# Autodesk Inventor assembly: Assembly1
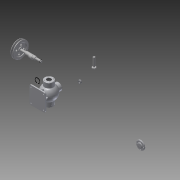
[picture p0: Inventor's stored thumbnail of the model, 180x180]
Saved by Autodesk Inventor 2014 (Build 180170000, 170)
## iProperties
Created: 2017-01
Part Number: Assembly1
Document SubType Name: Assembly
Designer: ksu
Author: ksu
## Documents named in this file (19)
- C:\Users\ksu\Desktop\470118V1012\Assembly1.iam
- C:\Users\ksu\Desktop\470118V1012\멈춤링- 15 x 1.ipt
- C:\Users\ksu\Desktop\470118V1012\멈춤링- 35x1.6.ipt
- KS B 1336 - 35x1.6.ipt
- C:\Users\ksu\Desktop\470118V1012\베어링- 6202.ipt
- KS B 2023 - 6202 - 15 x 35 x 11 - 7.8.ipt
- C:\Users\ksu\Desktop\470118V1012\본체.ipt
- C:\Users\ksu\Desktop\470118V1012\볼트 M4 x 12.ipt
- C:\Users\ksu\Desktop\470118V1012\볼트 M4 x 16.ipt
- C:\Users\ksu\Desktop\470118V1012\부시.ipt
- C:\Users\ksu\Desktop\470118V1012\상부커버.ipt
- C:\Users\ksu\Desktop\470118V1012\슬라이드.ipt
- C:\Users\ksu\Desktop\470118V1012\앞커버.ipt
- C:\Users\ksu\Desktop\470118V1012\오일실 15 30 7.ipt
- C:\Users\ksu\Desktop\470118V1012\키 4 x 4 x 12.ipt
- C:\Users\ksu\Desktop\470118V1012\편심축.ipt
- C:\Users\ksu\Desktop\470118V1012\V-벨트풀리.ipt
- C:\Users\ksu\Desktop\470118V1012\너트 M8.ipt
- C:\Users\ksu\Desktop\470118V1012\뒤커버.ipt
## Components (16 placed, 5 different names)
1. KS B 1336 - 35x1.6:1
2. KS B 2023 - 6202 - 15 x 35 x 11 - 7.8:1 — Mate:47, Mate:48
3. KS B 1021 - 에 따름 ISO 1207 - 미터 A  M 4 x 12:1 — Mate:25, Mate:44
4. ISO 4762 M4 x 16:1 — Mate:4, Mate:8
5. V-벨트풀리:1 — Mate:35, Mate:36
6. ISO 4762 M4 x 16:2 — Mate:11, Mate:12
7. ISO 4762 M4 x 16:3 — Mate:7, Mate:10
8. ISO 4762 M4 x 16:4 — Mate:6, Mate:9
9. ISO 4762 M4 x 16:5
10. ISO 4762 M4 x 16:6
11. ISO 4762 M4 x 16:7
12. ISO 4762 M4 x 16:8
13. KS B 1021 - 에 따름 ISO 1207 - 미터 A  M 4 x 12:2 — Mate:27, Mate:43
14. KS B 1021 - 에 따름 ISO 1207 - 미터 A  M 4 x 12:3 — Mate:26, Mate:45
15. KS B 1021 - 에 따름 ISO 1207 - 미터 A  M 4 x 12:4 — Mate:28, Mate:46
16. KS B 2023 - 6202 - 15 x 35 x 11 - 7.8:2 — Mate:49, Mate:50
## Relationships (22: Mate 22)
- Mate:4: ISO 4762 M4 x 16:1
- Mate:6: ISO 4762 M4 x 16:4
- Mate:7: ISO 4762 M4 x 16:3
- Mate:8: ISO 4762 M4 x 16:1
- Mate:9: ISO 4762 M4 x 16:4
- Mate:10: ISO 4762 M4 x 16:3
- Mate:11: ISO 4762 M4 x 16:2
- Mate:12: ISO 4762 M4 x 16:2
- Mate:25: KS B 1021 - 에 따름 ISO 1207 - 미터 A  M 4 x 12:1
- Mate:26: KS B 1021 - 에 따름 ISO 1207 - 미터 A  M 4 x 12:3
- Mate:27: KS B 1021 - 에 따름 ISO 1207 - 미터 A  M 4 x 12:2
- Mate:28: KS B 1021 - 에 따름 ISO 1207 - 미터 A  M 4 x 12:4
- Mate:35: V-벨트풀리:1
- Mate:36: V-벨트풀리:1
- Mate:43: KS B 1021 - 에 따름 ISO 1207 - 미터 A  M 4 x 12:2
- Mate:44: KS B 1021 - 에 따름 ISO 1207 - 미터 A  M 4 x 12:1
- Mate:45: KS B 1021 - 에 따름 ISO 1207 - 미터 A  M 4 x 12:3
- Mate:46: KS B 1021 - 에 따름 ISO 1207 - 미터 A  M 4 x 12:4
- Mate:47: KS B 2023 - 6202 - 15 x 35 x 11 - 7.8:1
- Mate:48: KS B 2023 - 6202 - 15 x 35 x 11 - 7.8:1
- Mate:49: KS B 2023 - 6202 - 15 x 35 x 11 - 7.8:2
- Mate:50: KS B 2023 - 6202 - 15 x 35 x 11 - 7.8:2
## Named parameters: d12_d3 = 0, d13_d5 = 0, d14_d6 = 0, d15_d7 = 0, d16_d8 = 0, d17_d9 = 0, d18_d10 = 0, d19_d11 = 0
